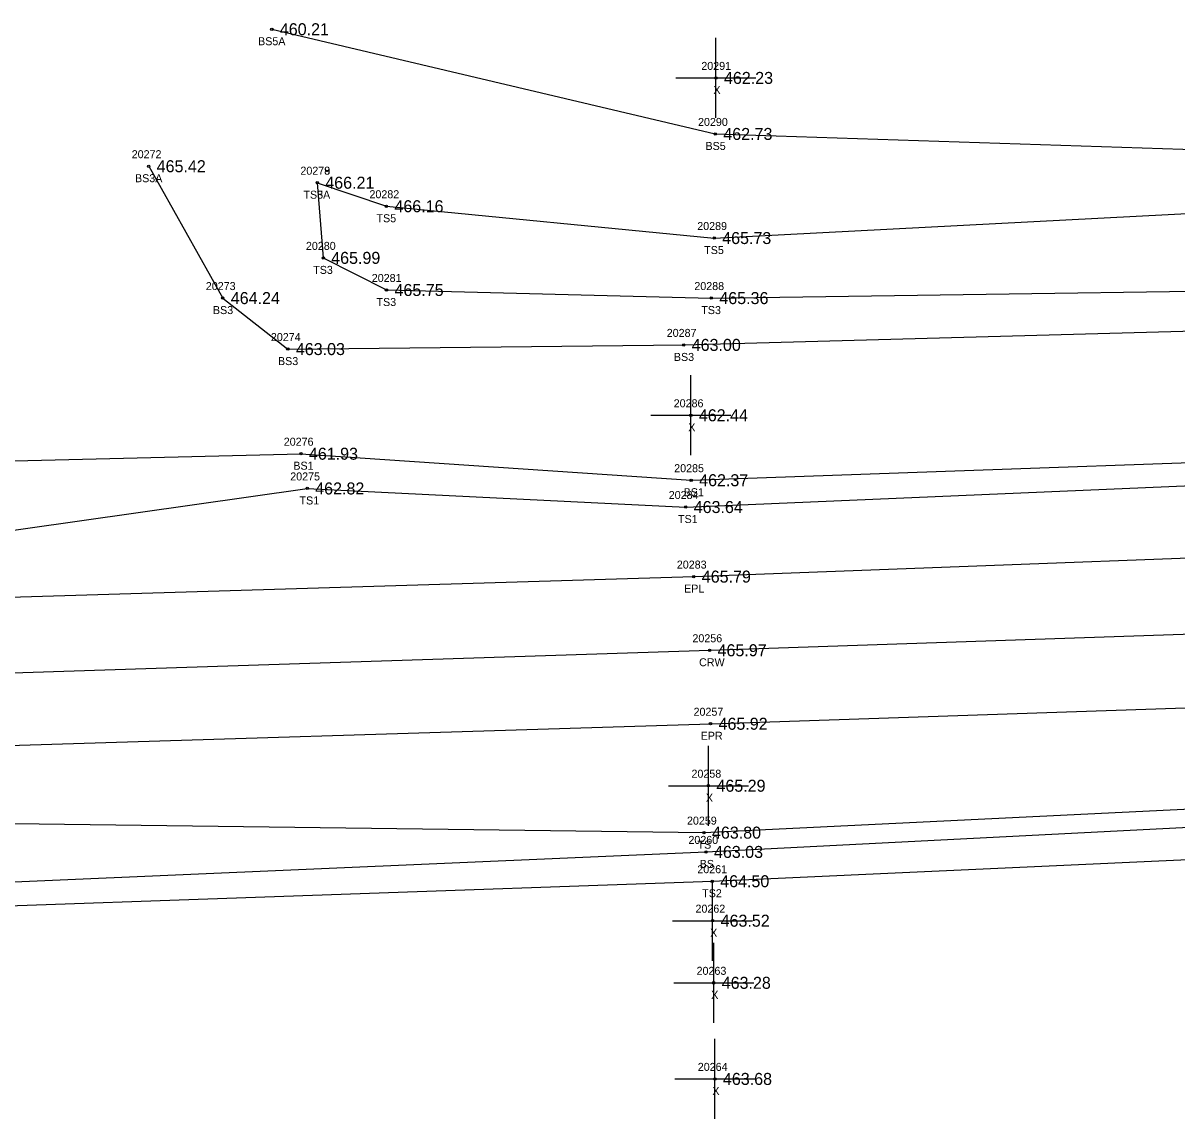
# Model space of a CAD drawing. Extents: x 1785066 to 1786589, y 770293 to 771312.
# Drawn here: x 1785893.3 to 1786037.5, y 770801.9 to 770938.8 of the extents above; entities that cross this region are included whole.
import ezdxf

# ---------------------------------------------------------------- set-up
doc = ezdxf.new("R2010")
doc.units = 0
for name, color, linetype in [('RD_DTM_BkLn1', 7, 'Continuous'), ('RD_DTM_BkLn2', 7, 'Continuous'), ('RD_DTM_BkLn_txCode', 7, 'Continuous'), ('RD_EX_Misc', 7, 'Continuous'), ('RD_EX_Misc_txCode', 7, 'Continuous'), ('RD_EX_Road', 7, 'Continuous'), ('RD_EX_Road_txCode', 7, 'Continuous'), ('RD_EX_TX_Misc_ELEV', 7, 'Continuous'), ('RD_EX_TX_Road_ELEV', 7, 'Continuous'), ('RD_HC_Survey_ELEV', 7, 'Continuous'), ('RD_HC_Survey_txCode', 7, 'Continuous'), ('RD_SMD_Locator', 7, 'Continuous')]:
    doc.layers.add(name, color=color, linetype=linetype)

msp = doc.modelspace()

# ---------------------------------------------------------------- linework, layer by layer
at = {"layer": 'RD_DTM_BkLn1'}
msp.add_lwpolyline([(1785825, 770854.98), (1785879.1, 770857.22), (1785979.05, 770860.47), (1786078.95, 770863.87), (1786178.85, 770867.23), (1786278.74, 770870.52), (1786378.69, 770873.93), (1786478.55, 770877.83), (1786578.48, 770880.72)], dxfattribs=at)
at = {"layer": 'RD_DTM_BkLn2'}
for points in [[(1785924.35, 770938.04), (1785979.77, 770924.96), (1786076.29, 770921.81), (1786177.35, 770923.09), (1786221.77, 770919.9), (1786240.57, 770915.48), (1786249.92, 770909.62), (1786247.47, 770900.2)], [(1785908.96, 770920.93), (1785918.22, 770904.46), (1785926.35, 770898.09), (1785975.82, 770898.61), (1786077.75, 770901.41), (1786177.29, 770903.98), (1786225.48, 770902.11), (1786247.47, 770900.2)], [(1785930.03, 770918.87), (1785930.77, 770909.48), (1785938.68, 770905.47), (1785979.27, 770904.46), (1786076.58, 770905.86), (1786177.7, 770910.56), (1786225.99, 770907)], [(1785930.03, 770918.87), (1785938.67, 770915.93), (1785979.63, 770911.96), (1786076.31, 770917), (1786177.99, 770915.82), (1786222.98, 770915.16), (1786240.32, 770910.21), (1786225.99, 770907)], [(1785823.92, 770890.03), (1785878.49, 770883.8), (1785927.98, 770885.02), (1785976.75, 770881.71), (1786078.01, 770885.31), (1786179.02, 770889.42), (1786277.82, 770892.61), (1786356.85, 770898.28)], [(1785823.56, 770878.59), (1785827.04, 770881.87), (1785879.17, 770873.62), (1785928.77, 770880.68), (1785976.07, 770878.36), (1786078.31, 770882.72), (1786179.21, 770888.23), (1786278, 770891.06), (1786358.22, 770894.11)], [(1785823.92, 770890.03), (1785823.56, 770878.59), (1785822.86, 770870.38), (1785821.44, 770840.38), (1785828.62, 770840.78), (1785842.19, 770836.7), (1785879.25, 770839.01), (1785978.35, 770837.69), (1786078.6, 770842.58), (1786178.83, 770845.52), (1786229.23, 770850.73), (1786230.88, 770847.03), (1786230.86, 770843.81)], [(1785827.67, 770829.52), (1785841.85, 770827.95), (1785844.56, 770828.57), (1785879.6, 770830.99), (1785978.6, 770835.28), (1786078.94, 770840.43), (1786179.05, 770843.41), (1786228.83, 770846.64)], [(1785823.45, 770822.61), (1785818.3, 770824.93), (1785815.32, 770825.6), (1785815.62, 770826.83), (1785818.45, 770825.65), (1785827.36, 770825.61), (1785879.44, 770828.14), (1785979.38, 770831.62), (1786079.14, 770836.17), (1786182.02, 770840.89), (1786230.86, 770843.81)]]:
    msp.add_lwpolyline(points, dxfattribs=at)
at = {"layer": 'RD_EX_Misc'}
for p, q in [((1785979.85, 770926.96), (1785979.85, 770936.96)), ((1785974.85, 770931.96), (1785984.85, 770931.96)), ((1785976.71, 770884.82), (1785976.71, 770894.82)), ((1785971.71, 770889.82), (1785981.71, 770889.82)), ((1785978.91, 770838.55), (1785978.91, 770848.55)), ((1785973.91, 770843.55), (1785983.91, 770843.55)), ((1785979.43, 770821.69), (1785979.43, 770831.69)), ((1785974.43, 770826.69), (1785984.43, 770826.69)), ((1785979.57, 770813.93), (1785979.57, 770823.93)), ((1785974.57, 770818.93), (1785984.57, 770818.93)), ((1785979.72, 770801.93), (1785979.72, 770811.93)), ((1785974.72, 770806.93), (1785984.72, 770806.93))]:
    msp.add_line(p, q, dxfattribs=at)
at = {"layer": 'RD_EX_Road'}
for points in [[(1785824.57, 770864.86), (1785879.1, 770866.73), (1785977.08, 770869.67), (1786078.78, 770873.52), (1786179.09, 770876.83), (1786278.08, 770880.28), (1786358.72, 770883.31), (1786381.38, 770883.94), (1786478.25, 770886.75), (1786578.04, 770889.63)], [(1785825.31, 770845.6), (1785879.29, 770848.18), (1785979.17, 770851.29), (1786079.29, 770854.66), (1786178.79, 770858.1), (1786233.56, 770860.16), (1786246.2, 770860.52), (1786278.61, 770861.3), (1786379.15, 770864.94), (1786479.01, 770868.57), (1786578.78, 770871.53)]]:
    msp.add_lwpolyline(points, dxfattribs=at)
at = {"layer": 'RD_SMD_Locator'}
for centre in [(1785924.35, 770938.04), (1785979.85, 770931.96), (1785979.77, 770924.96), (1785908.96, 770920.93), (1785930.03, 770918.87), (1785930.03, 770918.87), (1785938.67, 770915.93), (1785979.63, 770911.96), (1785930.77, 770909.48), (1785918.22, 770904.46), (1785938.68, 770905.47), (1785979.27, 770904.46), (1785975.82, 770898.61), (1785926.35, 770898.09), (1785976.71, 770889.82), (1785927.98, 770885.02), (1785976.75, 770881.71), (1785928.77, 770880.68), (1785976.07, 770878.36), (1785977.08, 770869.67), (1785979.05, 770860.47), (1785979.17, 770851.29), (1785978.91, 770843.55), (1785978.35, 770837.69), (1785978.6, 770835.28), (1785979.38, 770831.62), (1785979.43, 770826.69), (1785979.57, 770818.93), (1785979.72, 770806.93)]:
    msp.add_circle(centre, 0.15, dxfattribs=at)

# ---------------------------------------------------------------- texts
at = {"layer": 'RD_DTM_BkLn_txCode'}
for s, p in [('BS5A', (1785922.63, 770936.04)), ('20290', (1785977.61, 770925.96)), ('BS5', (1785978.54, 770922.96)), ('20272', (1785906.84, 770921.93)), ('20278', (1785927.92, 770919.87)), ('20279', (1785927.92, 770919.87)), ('BS3A', (1785907.25, 770918.93)), ('TS3A', (1785928.3, 770916.87)), ('TS5A', (1785928.3, 770916.87)), ('20282', (1785936.55, 770916.93)), ('TS5', (1785937.43, 770913.93)), ('20289', (1785977.51, 770912.96)), ('20280', (1785928.61, 770910.48)), ('TS5', (1785978.38, 770909.96)), ('TS3', (1785929.52, 770907.48)), ('20281', (1785936.84, 770906.47)), ('20273', (1785916.1, 770905.46)), ('20288', (1785977.15, 770905.46)), ('TS3', (1785937.43, 770903.47)), ('BS3', (1785916.99, 770902.46)), ('TS3', (1785978.02, 770902.46)), ('20274', (1785924.23, 770899.09)), ('20287', (1785973.7, 770899.61)), ('BS3', (1785974.59, 770896.61)), ('BS3', (1785925.12, 770896.09)), ('20276', (1785925.84, 770886.02)), ('BS1', (1785927.04, 770883.02)), ('20285', (1785974.63, 770882.71)), ('20275', (1785926.65, 770881.68)), ('20284', (1785973.95, 770879.36)), ('BS1', (1785975.81, 770879.71)), ('TS1', (1785927.81, 770878.68)), ('TS1', (1785975.11, 770876.36)), ('20259', (1785976.23, 770838.69)), ('20260', (1785976.41, 770836.28)), ('TS', (1785977.55, 770835.69)), ('BS', (1785977.82, 770833.28)), ('20261', (1785977.52, 770832.62)), ('TS2', (1785978.13, 770829.62))]:
    msp.add_text(s, height=1, dxfattribs=at).set_placement(p)
at = {"layer": 'RD_EX_Misc_txCode'}
for s, p in [('20291', (1785978.02, 770932.96)), ('X', (1785979.53, 770929.96)), ('20286', (1785974.57, 770890.82)), ('X', (1785976.39, 770887.82)), ('20258', (1785976.79, 770844.55)), ('X', (1785978.59, 770841.55)), ('20262', (1785977.29, 770827.69)), ('X', (1785979.12, 770824.69)), ('20263', (1785977.43, 770819.93)), ('X', (1785979.25, 770816.93)), ('20264', (1785977.58, 770807.93)), ('X', (1785979.4, 770804.93))]:
    msp.add_text(s, height=1, dxfattribs=at).set_placement(p)
at = {"layer": 'RD_EX_Road_txCode'}
for s, p in [('20283', (1785974.96, 770870.67)), ('EPL', (1785975.87, 770867.67)), ('20257', (1785977.05, 770852.29)), ('EPR', (1785977.94, 770849.29))]:
    msp.add_text(s, height=1, dxfattribs=at).set_placement(p)
at = {"layer": 'RD_EX_TX_Misc_ELEV'}
for s, p in [('460.21', (1785925.35, 770937.29)), ('462.23', (1785980.85, 770931.21)), ('462.73', (1785980.77, 770924.21)), ('465.42', (1785909.96, 770920.18)), ('466.21', (1785931.03, 770918.12)), ('466.21', (1785931.03, 770918.12)), ('466.16', (1785939.67, 770915.18)), ('465.73', (1785980.63, 770911.21)), ('465.99', (1785931.77, 770908.73)), ('465.75', (1785939.68, 770904.72)), ('464.24', (1785919.22, 770903.71)), ('465.36', (1785980.27, 770903.71)), ('463.03', (1785927.35, 770897.34)), ('463.00', (1785976.82, 770897.86)), ('462.44', (1785977.71, 770889.07)), ('461.93', (1785928.98, 770884.27)), ('462.82', (1785929.77, 770879.93)), ('462.37', (1785977.75, 770880.96)), ('463.64', (1785977.07, 770877.61)), ('465.29', (1785979.91, 770842.8)), ('463.80', (1785979.35, 770836.94)), ('463.03', (1785979.6, 770834.53)), ('464.50', (1785980.38, 770830.87)), ('463.52', (1785980.43, 770825.94)), ('463.28', (1785980.57, 770818.18)), ('463.68', (1785980.72, 770806.18))]:
    msp.add_text(s, height=1.5, dxfattribs=at).set_placement(p)
at = {"layer": 'RD_EX_TX_Road_ELEV'}
for s, p in [('465.79', (1785978.08, 770868.92)), ('465.92', (1785980.17, 770850.54))]:
    msp.add_text(s, height=1.5, dxfattribs=at).set_placement(p)
at = {"layer": 'RD_HC_Survey_ELEV'}
msp.add_text('465.97', height=1.5, dxfattribs=at).set_placement((1785980.05, 770859.72))
at = {"layer": 'RD_HC_Survey_txCode'}
for s, p in [('20256', (1785976.91, 770861.47)), ('CRW', (1785977.74, 770858.47))]:
    msp.add_text(s, height=1, dxfattribs=at).set_placement(p)

doc.saveas('drawing.dxf')
